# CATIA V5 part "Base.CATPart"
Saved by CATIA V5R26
Part number: Part1
Bounding box of the stored display mesh (mm): x -50 to 50, y -25 to 25, z 0 to 50
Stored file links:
  D:\_Deepak\CATIA\CATIA V5-6R2016_Deepak\Resources\Part files\Partfiles\c12_catia_v5_6r2016_prt\c12_catia_v5-6r2016 figr_12-8\Base.CATPart
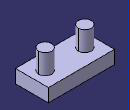
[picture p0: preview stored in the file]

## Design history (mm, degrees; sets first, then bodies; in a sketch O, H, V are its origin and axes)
Body1 (main body)
  Sketch1 on xy-plane, origin (0, 0, 0), H (1, 0, 0), V (0, 1, 0)
    line L1 (50, 25) -> (50, -25)
    line L2 (50, -25) -> (-50, -25)
    line L3 (-50, -25) -> (-50, 25)
    line L4 (-50, 25) -> (50, 25)
    circle A1 centre (-30, 0) radius 10
    point P5 (-30, 0)
    circle A2 centre (30, 0) radius 10
    length L2 = 100
    length L1 = 50
    radius A1 = 10
    distance P5 V = 30
    vertical: L1 V, L3 V
    horizontal: L2 H, L4 H
    equidistance: L1 L3 O, L2 L4 O
    coincidence: P5 H
    symmetry: A1 A2 V
  MultiPad1: profile Sketch1, domains (length 20; length 50; length 50)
